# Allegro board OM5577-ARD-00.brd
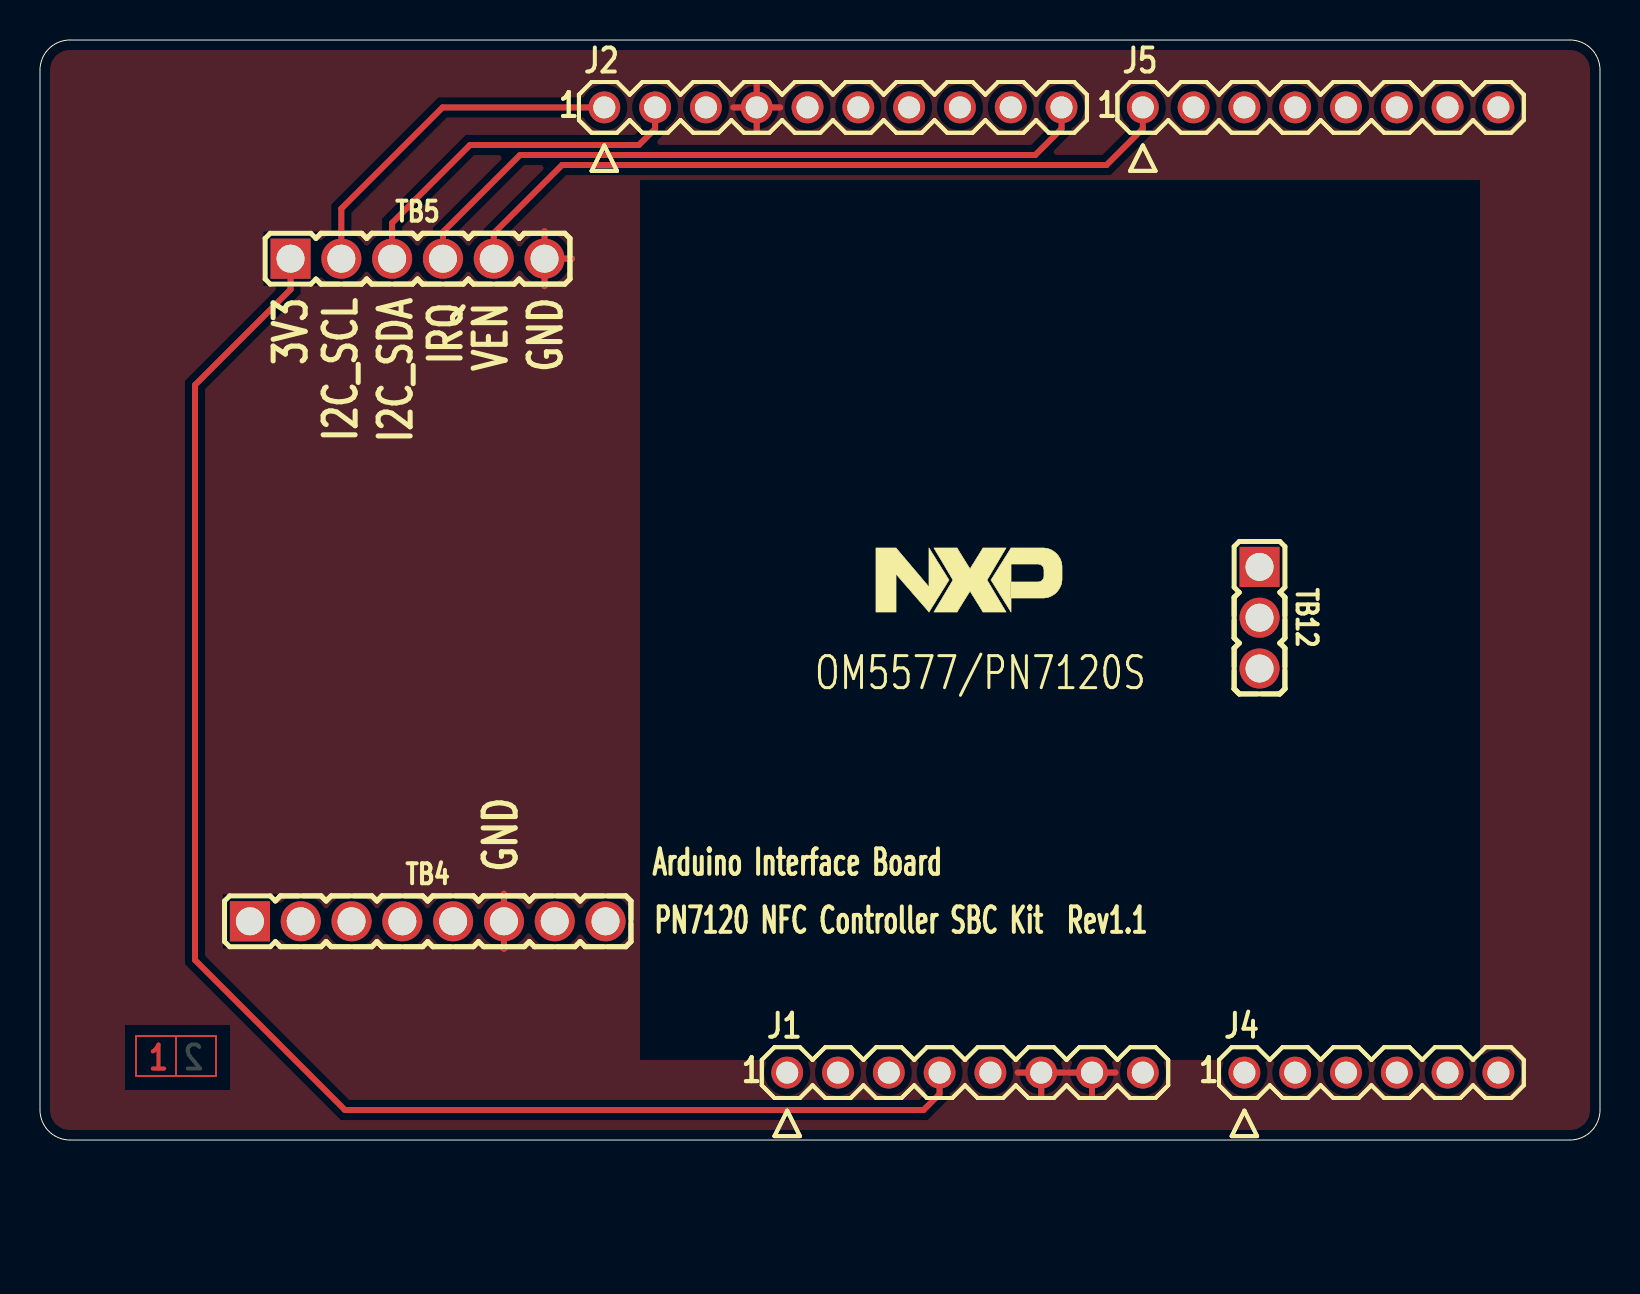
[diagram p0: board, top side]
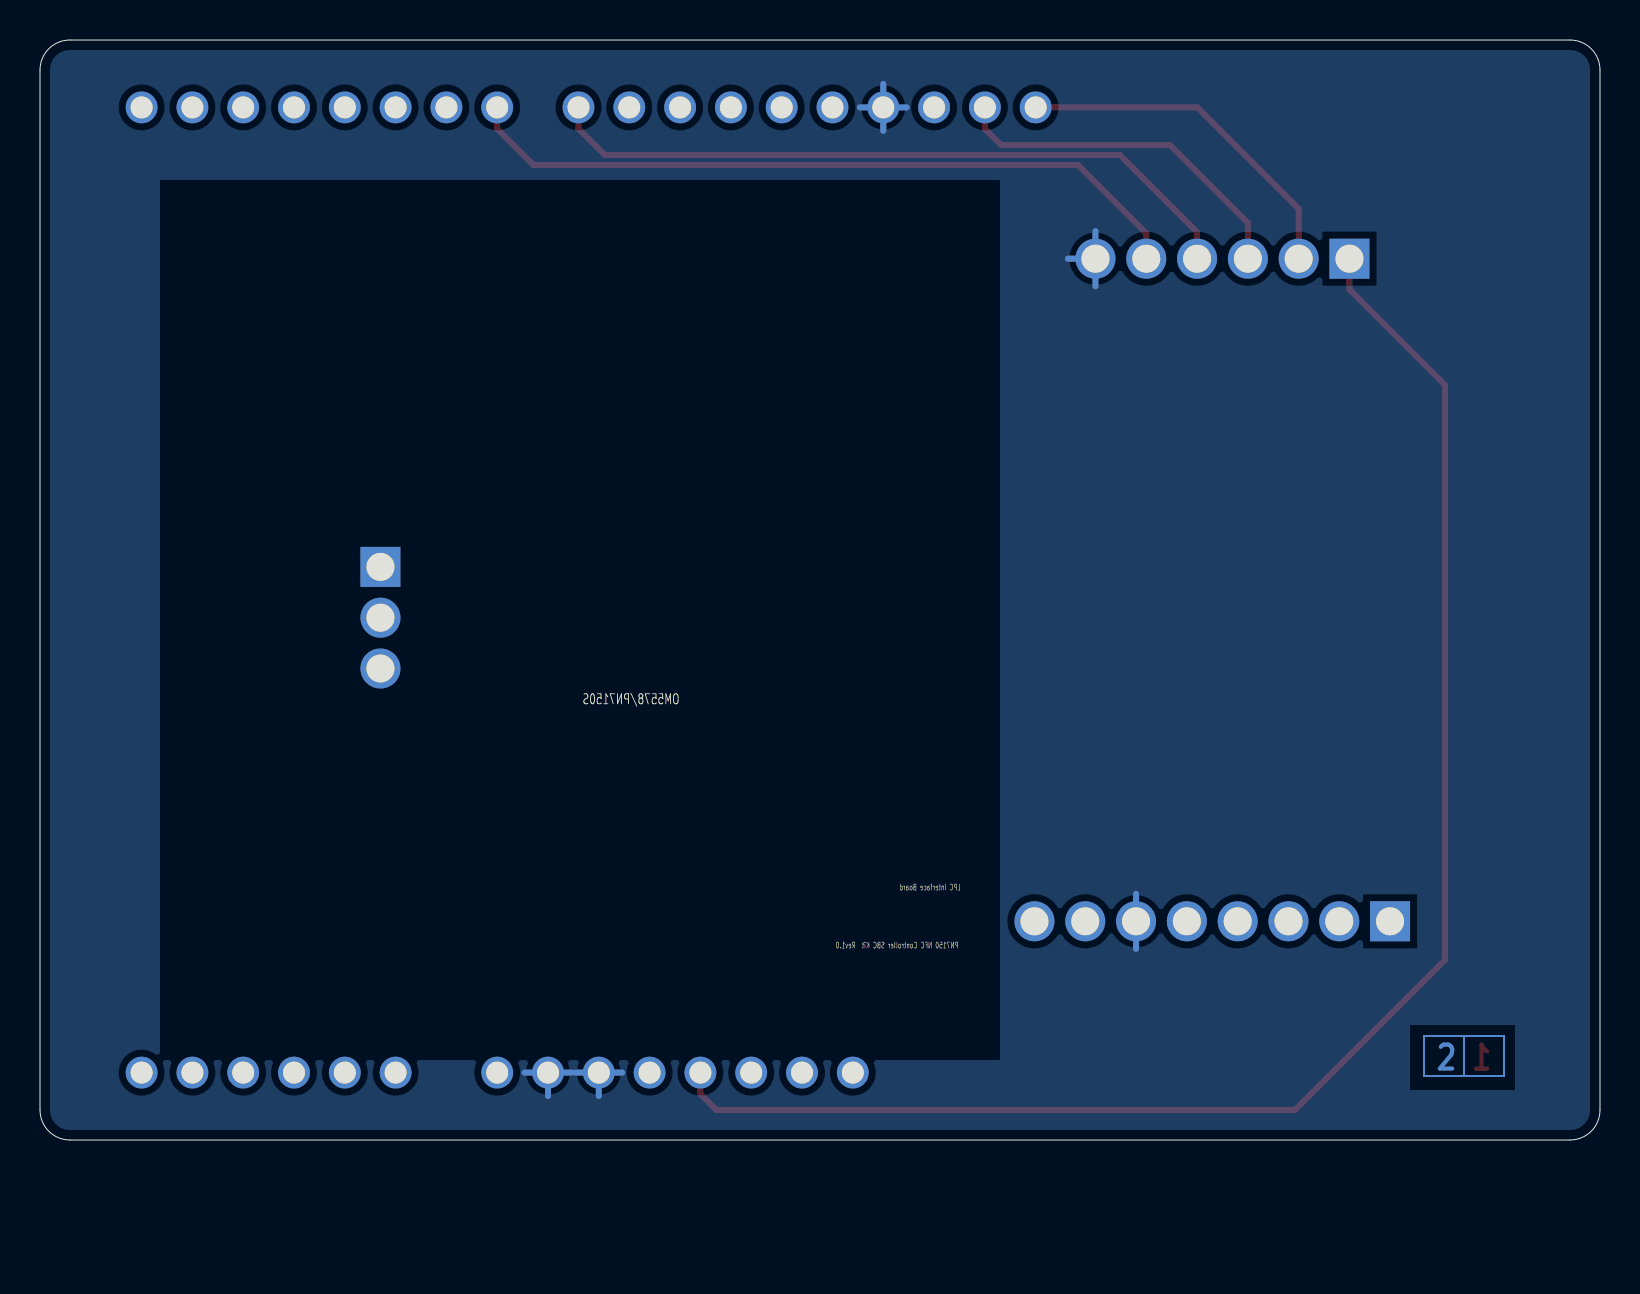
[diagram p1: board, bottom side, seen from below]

Outline 78 x 55 mm; copper layers: TOP, BOTTOM. Coordinates in mm from the lower left corner of the outline.
Outline path: 0,53.5 arc(0.44,54.56) 1.5,55 76.5,55 arc(77.56,54.56) 78,53.5 78,1.5 arc(77.56,0.44) 76.5,0 1.5,0 arc(0.44,0.44) 0,1.5 0,53.5

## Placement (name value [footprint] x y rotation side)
1  BUBBLE1  [BUBBLE_DIAM8]  8.6 -5.7 0 top
J1  Con 1 x 8  [CON_BAR_254_8_MD]  46.25 3.37 0 top
J2  Con 1 x 10  [CON_BAR_254_10_MD]  39.65 51.63 0 top
J3  Con 1 x 6  [CON_BAR_254_6_MD]  66.57 3.37 0 top
J4  Con 1 x 8  [CON_BAR_254_8_MD]  64.03 51.63 0 top
NOREF  -  []  0 8.06 0 top
NOREF#2  -  []  0 53.5 0 top
NOREF#3  -  []  4.3 3.2 0 top
NOREF#4  -  []  10 0 90 top
NOREF#5  -  []  46.5 28 0 top
NOREF#6  -  []  -116.2 -191.6 0 top
NOREF#7  -  []  76.5 0 90 top
TB4  FORK  [AGPS1-08-BSE]  10.5 10.94 0 top
TB5  FORK  [AGPS1-06-BSE]  12.53 44.06 0 top
TB12  FORK  [AGPS1-03-BSE]  60.98 28.66 270 top

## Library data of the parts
1 = BUBBLE_CI: alternate symbols: (BUBBLE_DIAM4)
J1 J4 = Con 1 x 8
J2 = Con 1 x 10
J3 = Con 1 x 6
TB4 = bar_1x8_MD: Tolerance: TOLERANCE; User Part Number: PARTNUM
TB5 = bar_1x6_MD: Tolerance: TOLERANCE; User Part Number: PARTNUM
TB12 = bar_1x3_MD: Tolerance: TOLERANCE; User Part Number: PARTNUM

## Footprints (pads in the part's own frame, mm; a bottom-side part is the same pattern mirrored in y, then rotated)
AGPS1-03-BSE
  rect 2x2 hole 1.4: 1(0,0)
  round 2 hole 1.4: 2(2.54,0) 3(5.08,0)
AGPS1-06-BSE
  rect 2x2 hole 1.4: 1(0,0)
  round 2 hole 1.4: 2(2.54,0) 3(5.08,0) 4(7.62,0) 5(10.16,0) 6(12.7,0)
AGPS1-08-BSE
  rect 2x2 hole 1.4: 1(0,0)
  round 2 hole 1.4: 2(2.54,0) 3(5.08,0) 4(7.62,0) 5(10.16,0) 6(12.7,0) 7(15.24,0) 8(17.78,0)
BUBBLE_DIAM8
  round 0 smd: 1(0,0)
CON_BAR_254_6_MD
  round 1.59 hole 1.1: 1(-6.35,0) 2(-3.81,0) 3(-1.27,0) 4(1.27,0) 5(3.81,0) 6(6.35,0)
CON_BAR_254_8_MD
  round 1.59 hole 1.1: 1(-8.89,0) 2(-6.35,0) 3(-3.81,0) 4(-1.27,0) 5(1.27,0) 6(3.81,0) 7(6.35,0) 8(8.89,0)
CON_BAR_254_10_MD
  round 1.59 hole 1.1: 1(-11.43,0) 2(-8.89,0) 3(-6.35,0) 4(-3.81,0) 5(-1.27,0) 6(1.27,0) 7(3.81,0) 8(6.35,0) 9(8.89,0) 10(11.43,0)

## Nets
GND: J1.6 J1.7 J2.4 TB4.6 TB5.6
VBAT_PVDD: J1.4 TB5.1
I2C_SCL: J2.1 TB5.2
I2C_SDA: J2.2 TB5.3
IRQ: J2.10 TB5.4
VEN: J4.1 TB5.5

Pads without a net: 1 1; J1 1 2 3 5 8; J2 3 5 6 7 8 9; J3 1 2 3 4 5 6; J4 2 3 4 5 6 7 8; TB4 1 2 3 4 5 7 8; TB12 1 2 3

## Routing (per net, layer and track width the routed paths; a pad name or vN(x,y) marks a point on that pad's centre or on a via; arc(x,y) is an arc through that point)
GND: length 37.2
  TOP w0.3: TB5.6 26.6,44.06 ; TB5.6 25.23,42.69 ; TB5.6 25.23,45.44 ; 35.84,50.46 J2.4 ; J2.4 37.01,51.63 ; J2.4 35.84,52.8 ; J2.4 34.66,51.63 ; J1.7 53.77,3.37 ; J1.7 52.6,2.2 ; J1.7 51.43,3.37 ; J1.6 51.23,3.37 ; J1.6 48.89,3.37 ; J1.6 50.06,2.2 ; 23.2,12.31 TB4.6 23.2,9.56
  BOTTOM w0.3: 34.66,51.63 J2.4 ; J2.4 35.84,50.46 ; J2.4 35.84,52.8 ; J2.4 37.01,51.63 ; TB5.6 26.6,44.06 ; TB5.6 25.23,42.69 ; TB5.6 25.23,45.44 ; 51.43,3.37 J1.7 ; J1.7 52.6,2.2 ; J1.7 53.77,3.37 ; 50.06,2.2 J1.6 ; J1.6 51.23,3.37 ; J1.6 48.89,3.37 ; 23.2,12.31 TB4.6 23.2,9.56
VBAT_PVDD: length 78.8
  TOP w0.3: TB5.1 12.53,42.53 7.75,37.75 7.75,9 15.25,1.5 44.18,1.5 44.98,2.3 J1.4
I2C_SCL: length 17.7
  TOP w0.3: TB5.2 15.07,46.57 20.13,51.63 J2.1
I2C_SDA: length 18
  TOP w0.3: J2.2 30.76,50.56 29.94,49.75 21.5,49.75 17.61,45.86 TB5.3
IRQ: length 35.5
  TOP w0.3: TB5.4 20.15,45.4 24,49.25 49.76,49.25 51.08,50.56 J2.10
VEN: length 37
  TOP w0.3: TB5.5 22.69,45.34 26.1,48.75 53.33,48.75 55.14,50.56 J4.1

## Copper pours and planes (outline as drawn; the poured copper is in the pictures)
GND on TOP: 0.5,53.5 0.79,54.21 1.5,54.5 76.5,54.5 77.21,54.21 77.5,53.5 77.5,1.5 77.21,0.79 76.5,0.5 1.5,0.5 0.79,0.79 0.5,1.5 ; 2 cut-outs
GND on BOTTOM: 0.5,53.5 0.79,54.21 1.5,54.5 76.5,54.5 77.21,54.21 77.5,53.5 77.5,1.5 77.21,0.79 76.5,0.5 1.5,0.5 0.79,0.79 0.5,1.5 ; 2 cut-outs

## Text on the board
Ref Des/Assembly Bottom: 1
Ref Des/Silkscreen Bottom: LPC Interface Board | PN7150 NFC Controller SBC Kit  Rev1.0 | OM5578/PN7150S
User.Comments: CR_INTERFACE_2 | CR_CONN_1
Ref Des/Silkscreen Top: Arduino Interface Board | PN7120 NFC Controller SBC Kit  Rev1.1 | OM5577/PN7120S | 3V3 | I2C_SCL | I2C_SDA | IRQ | VEN | GND
XSECTION_CHART: *  SURFACE - AIR 0 MM | L1: TOP CONDUCTOR - COPPER 0.018 MM | *  DIELECTRIC - FR-4 TBD | L2: BOTTOM CONDUCTOR - COPPER 0.018 MM | DESIGN CROSS SECTION CHART | ___________________________ | TOTAL THICKNESS 1.6 MM +/-10% | 1-2
User.6: TITRE | TITLE | . | No EVOL | DESSINE/DRAWN | SR_ASCO | REV. | Nbr/Qty | DATE | 01-02-2016 | EVOLUTION/CHANGE | J.GESLIN | VERIFIE/CHECKED | NUMERO DOCUMENT/DOCUMENT NUMBER | DESS./DRAWN | APPROUVE/APPROVED | ..-..-.... | VERIF./CHECKED | PAGE | Arduino Interface Board | 2 Esplanade Anton Philips | BP 2000 - COLOMBELLES | 14906 CAEN CEDEX 9 | SEMICONDUCTORS | OM5577ARD | / | 00
User.7: 1 | 2 | TOP LAYER | 311
User.8: 2 | BOTTOM LAYER | 311
User.9: 2 | 4 | LAYER2 | 311
User.10: 3 | 4 | LAYER3 | 311
User.21: 2 | 380 | SILKSCREEN BOT
User.22: 1 | SILKSCREEN TOP | 380
User.23: 2 | SOLDERMASK BOT | 312
User.24: 2 | PASTEMASK BOT | 435
User.26: 1 | 2 | PASTEMASK TOP | 435
User.28: 1 | 2 | SOLDERMASK TOP | 312
User.29: 1 | DETOURAGE | 313
User.33: 1 | 2 | ASSEMBLY TOP | 400
User.36: 2 | 400 | ASSEMBLY BOT
User.38: All rights are reserved. Reproduction in | whole or in part is prohibited without | the written consent of the copyright owner | Date : 01-02-2016 | Draw by : ASCO_SR | Checked by: J.GESLIN | Project : OM5577ARD | Material:FR4 TG150 LOW CTEz | Protection : SOLDERMASK | 16/10 17.5 uM of basic | Finition : NI/Au chemical | TOP BOTTOM | Marging : +/-0.1 | Manufact.level : 5 | Scale : 1/1 | Nbr of layers : 2 | Silkscreen | TOP   :YES | BOTTOM:NO | NXP Semiconductors | 2,Esplanade Anton Philips | Campus Effiscience Colombelles | BP 2000 - 14906 CAEN CEDEX 9 | Date | Draw by | Verify | Modifications | SIZE | REV. | IND. | PL. | Arduino Interface Board | DRILL MANUFACTURING | H | G | F | E | D | C | B | A | 4 | 3 | 2 | 1 | A3 | OM5577ARD-300 | 00
User.39: . | TITRE | TITLE | PAGE | 09-10-2015 | DATE | VERIF./CHECKED | REV. | ..-..-.... | J.GESLIN | APPROUVE/APPROVED | DESS./DRAWN | NUMERO DOCUMENT/DOCUMENT NUMBER | VERIFIE/CHECKED | EVOLUTION/CHANGE | Nbr/Qty | GL_ASCO | DESSINE/DRAWN | No EVOL | LPC Interface Board | SEMICONDUCTORS | 2 Esplanade Anton Philips | BP 2000 - COLOMBELLES | 14906 CAEN CEDEX 9 | / | OM29110ARD | 00
User.45: SH1 | L104 | Y1 | C56 | R32 | R24 | U1 | C10 | C19 | C20 | C52 | C16 | C15 | R53 | C53 | C55 | C54 | C12 | R54 | C11 | C57 | C1 | C22 | C2 | R23 | C8 | C3 | C7 | C9 | C21 | C6 | L2 | L1 | C14 | C13 | R1 | R2 | C51 | C50 | C18 | C17 | R56 | TB1 | R75 | R73 | R55 | RaspberryPi Interface Board | PN7120 NFC Controller SBC Kit  Rev1.1 | OM5577ARD | . | 00 | 380 | 2 | 1 | 25 | OM5577/PN7120S | GND | 3V3 | SCL | SDA | GPIO23 | GPIO24 | FIGURE | SIZE | 1.1 | 1.4 | DRILL CHART: TOP to BOTTOM | ALL UNITS ARE IN MILLIMETERS | TOLERANCE | +0.1/-0.05 | +0.0/-0.0 | PLATED | QTY | 32 | 17
